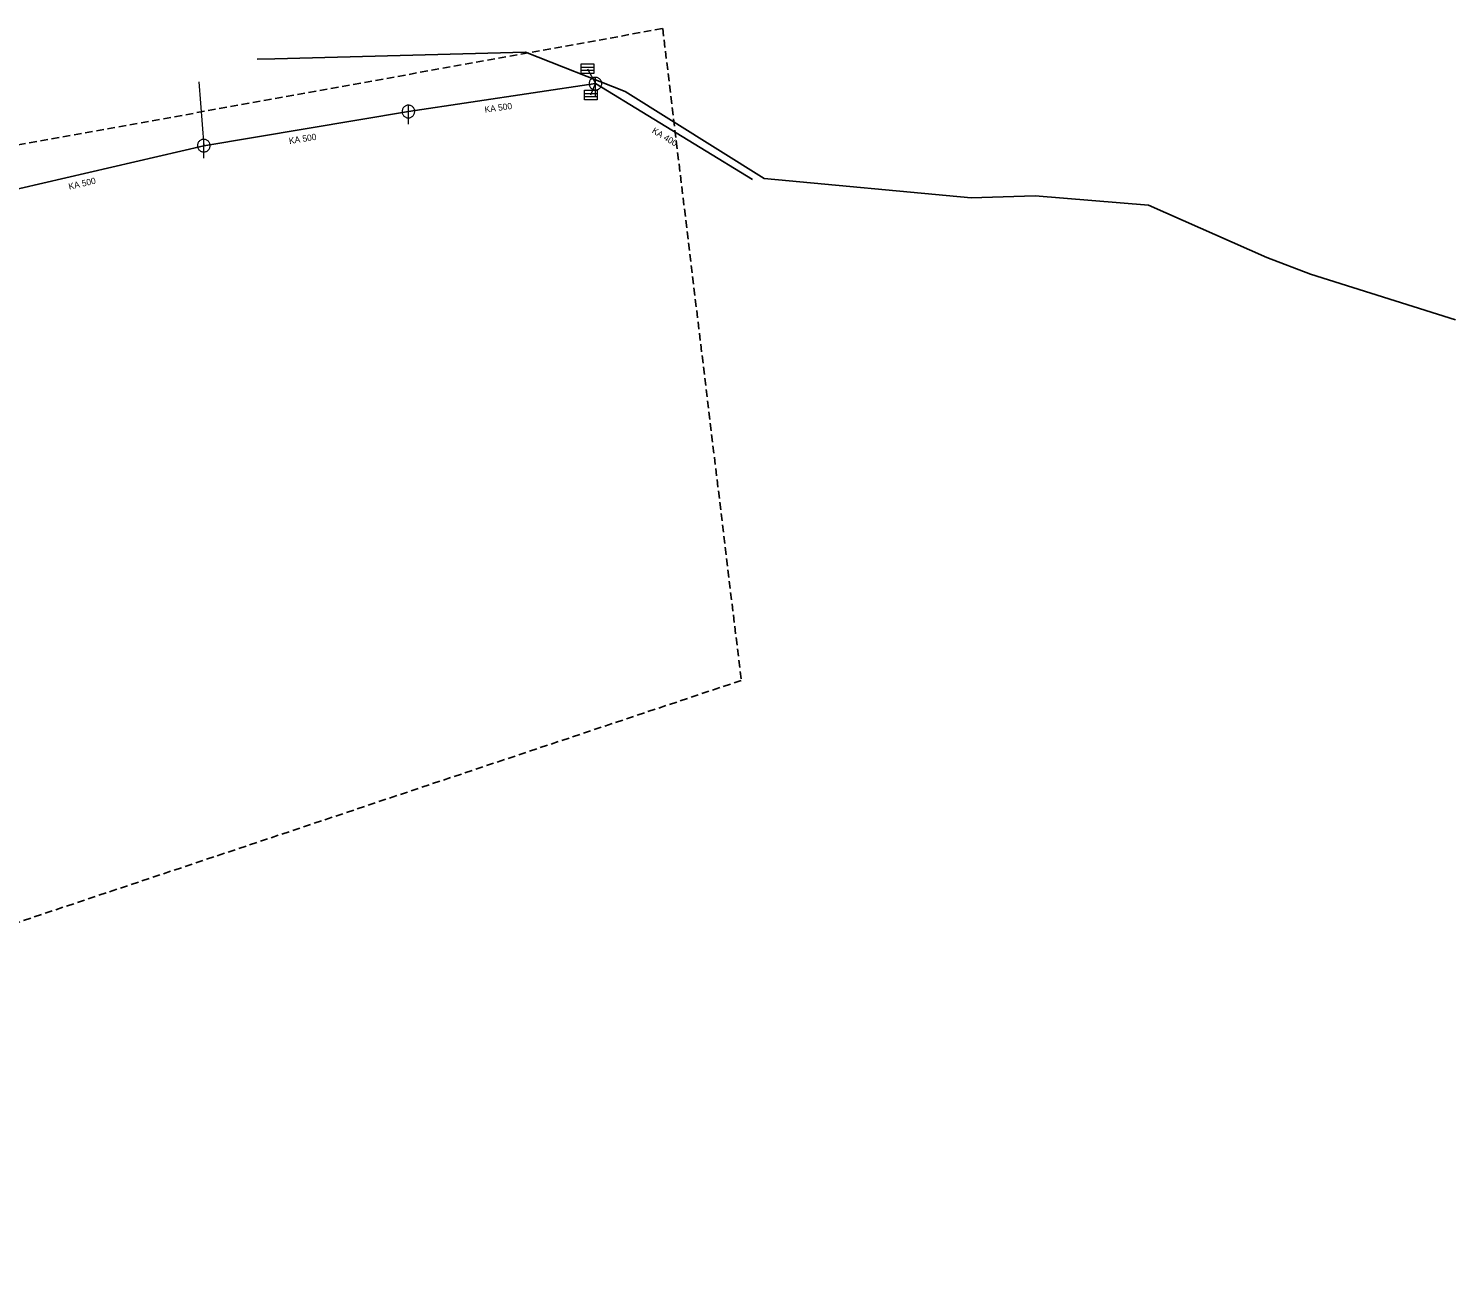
# Model space of a CAD drawing. Extents: x -687013 to -686506, y -973869 to -973672.
# Drawn here: x -686732.6 to -686506.3, y -973869.4 to -973671.6 of the extents above; entities that cross this region are included whole.
import ezdxf

# ---------------------------------------------------------------- set-up
doc = ezdxf.new("R2010")
doc.units = 0
doc.header["$LTSCALE"] = 0.4
doc.linetypes.add('MEDIUM_DASHED', pattern=[4.5, 3, -1.5])
doc.layers.add('1', color=7, linetype='Continuous')
for name, color, linetype, lineweight in [('11', 7, 'Continuous', 13), ('14', 7, 'Continuous', 25), ('17', 7, 'Continuous', 25), ('22', 7, 'Continuous', 13), ('63', 7, 'MEDIUM_DASHED', 25)]:
    doc.layers.add(name, color=color, linetype=linetype, lineweight=lineweight)

msp = doc.modelspace()

# ---------------------------------------------------------------- linework, layer by layer
at = {"layer": '11'}
for p, q in [((-686643.98, -973677.98), (-686642.71, -973680.34)), ((-686705.62, -973680.08), (-686704.81, -973690.17)), ((-686643.45, -973682.14), (-686642.71, -973680.34))]:
    msp.add_line(p, q, dxfattribs=at)
at = {"layer": '14'}
for p, q in [((-686642.71, -973680.34), (-686672.372, -973684.756)), ((-686617.8, -973695.539), (-686642.71, -973680.34)), ((-686672.372, -973684.756), (-686704.809, -973690.17)), ((-686704.809, -973690.17), (-686742.511, -973698.919))]:
    msp.add_line(p, q, dxfattribs=at)
at = {"layer": '17'}
msp.add_lwpolyline([(-686506.346, -973717.746), (-686529.344, -973710.524), (-686536.247, -973707.872), (-686555.026, -973699.577), (-686572.978, -973698.129), (-686583.112, -973698.418), (-686615.962, -973695.359), (-686637.993, -973681.581), (-686653.818, -973675.34), (-686693.532, -973676.405), (-686696.345, -973676.48)], dxfattribs=at)
at = {"layer": '22'}
for p, q in [((-686644.991, -973677.723), (-686642.991, -973677.723)), ((-686644.991, -973678.223), (-686642.991, -973678.223)), ((-686642.71, -973682.34), (-686642.709, -973679.34)), ((-686644.461, -973681.883), (-686642.461, -973681.883)), ((-686644.461, -973682.383), (-686642.461, -973682.383)), ((-686672.372, -973686.757), (-686672.371, -973683.757)), ((-686704.81, -973692.17), (-686704.809, -973689.17))]:
    msp.add_line(p, q, dxfattribs=at)
for points in [[(-686644.991, -973677.223), (-686642.991, -973677.223), (-686642.991, -973678.723), (-686644.991, -973678.723)], [(-686641.71, -973680.34), (-686641.715, -973680.231), (-686641.733, -973680.123), (-686641.763, -973680.017), (-686641.803, -973679.916), (-686641.855, -973679.819), (-686641.917, -973679.729), (-686641.989, -973679.646), (-686642.069, -973679.572), (-686642.157, -973679.506), (-686642.251, -973679.451), (-686642.351, -973679.406), (-686642.456, -973679.373), (-686642.563, -973679.351), (-686642.672, -973679.341), (-686642.782, -973679.343), (-686642.89, -973679.357), (-686642.997, -973679.382), (-686643.1, -973679.419), (-686643.198, -973679.468), (-686643.29, -973679.526), (-686643.376, -973679.595), (-686643.453, -973679.672), (-686643.522, -973679.758), (-686643.581, -973679.85), (-686643.629, -973679.948), (-686643.666, -973680.051), (-686643.692, -973680.158), (-686643.706, -973680.266), (-686643.709, -973680.376), (-686643.699, -973680.485), (-686643.678, -973680.592), (-686643.644, -973680.696), (-686643.6, -973680.796), (-686643.545, -973680.891), (-686643.479, -973680.979), (-686643.405, -973681.059), (-686643.322, -973681.131), (-686643.232, -973681.193), (-686643.136, -973681.245), (-686643.034, -973681.286), (-686642.929, -973681.316), (-686642.821, -973681.334), (-686642.711, -973681.34), (-686642.602, -973681.334), (-686642.494, -973681.316), (-686642.389, -973681.287), (-686642.287, -973681.246), (-686642.19, -973681.194), (-686642.1, -973681.132), (-686642.017, -973681.061), (-686641.942, -973680.981), (-686641.877, -973680.893), (-686641.821, -973680.799), (-686641.777, -973680.699), (-686641.743, -973680.595), (-686641.721, -973680.487), (-686641.711, -973680.378)], [(-686644.461, -973681.383), (-686642.461, -973681.383), (-686642.461, -973682.883), (-686644.461, -973682.883)], [(-686671.372, -973684.757), (-686671.377, -973684.648), (-686671.395, -973684.54), (-686671.425, -973684.434), (-686671.465, -973684.333), (-686671.517, -973684.236), (-686671.579, -973684.146), (-686671.651, -973684.063), (-686671.731, -973683.989), (-686671.819, -973683.923), (-686671.913, -973683.868), (-686672.013, -973683.823), (-686672.118, -973683.79), (-686672.225, -973683.768), (-686672.334, -973683.758), (-686672.444, -973683.76), (-686672.552, -973683.774), (-686672.659, -973683.799), (-686672.762, -973683.836), (-686672.86, -973683.885), (-686672.952, -973683.943), (-686673.038, -973684.012), (-686673.115, -973684.089), (-686673.184, -973684.175), (-686673.243, -973684.267), (-686673.291, -973684.365), (-686673.328, -973684.468), (-686673.354, -973684.575), (-686673.368, -973684.683), (-686673.371, -973684.793), (-686673.361, -973684.902), (-686673.34, -973685.009), (-686673.306, -973685.113), (-686673.262, -973685.213), (-686673.207, -973685.308), (-686673.141, -973685.396), (-686673.067, -973685.476), (-686672.984, -973685.548), (-686672.894, -973685.61), (-686672.798, -973685.662), (-686672.696, -973685.703), (-686672.591, -973685.733), (-686672.483, -973685.751), (-686672.373, -973685.757), (-686672.264, -973685.751), (-686672.156, -973685.733), (-686672.051, -973685.704), (-686671.949, -973685.663), (-686671.852, -973685.611), (-686671.762, -973685.549), (-686671.679, -973685.478), (-686671.604, -973685.398), (-686671.539, -973685.31), (-686671.483, -973685.216), (-686671.439, -973685.116), (-686671.405, -973685.012), (-686671.383, -973684.904), (-686671.373, -973684.795)], [(-686703.81, -973690.17), (-686703.815, -973690.061), (-686703.833, -973689.953), (-686703.863, -973689.847), (-686703.903, -973689.746), (-686703.955, -973689.649), (-686704.017, -973689.559), (-686704.089, -973689.476), (-686704.169, -973689.402), (-686704.257, -973689.336), (-686704.351, -973689.281), (-686704.451, -973689.236), (-686704.556, -973689.203), (-686704.663, -973689.181), (-686704.772, -973689.171), (-686704.882, -973689.173), (-686704.99, -973689.187), (-686705.097, -973689.212), (-686705.2, -973689.249), (-686705.298, -973689.298), (-686705.39, -973689.356), (-686705.476, -973689.425), (-686705.553, -973689.502), (-686705.622, -973689.588), (-686705.681, -973689.68), (-686705.729, -973689.778), (-686705.766, -973689.881), (-686705.792, -973689.988), (-686705.806, -973690.096), (-686705.809, -973690.206), (-686705.799, -973690.315), (-686705.778, -973690.422), (-686705.744, -973690.526), (-686705.7, -973690.626), (-686705.645, -973690.721), (-686705.579, -973690.809), (-686705.505, -973690.889), (-686705.422, -973690.961), (-686705.332, -973691.023), (-686705.236, -973691.075), (-686705.134, -973691.116), (-686705.029, -973691.146), (-686704.921, -973691.164), (-686704.811, -973691.17), (-686704.702, -973691.164), (-686704.594, -973691.146), (-686704.489, -973691.117), (-686704.387, -973691.076), (-686704.29, -973691.024), (-686704.2, -973690.962), (-686704.117, -973690.891), (-686704.042, -973690.811), (-686703.977, -973690.723), (-686703.921, -973690.629), (-686703.877, -973690.529), (-686703.843, -973690.425), (-686703.821, -973690.317), (-686703.811, -973690.208)]]:
    msp.add_lwpolyline(points, close=True, dxfattribs=at)
at = {"layer": '63'}
msp.add_lwpolyline([(-686909.784, -973869.363), (-686968.065, -973779.329), (-686968.065, -973779.329), (-686933.901, -973735.117), (-686933.901, -973735.117), (-686846.279, -973716.226), (-686846.279, -973716.226), (-686793.223, -973715.824), (-686793.223, -973715.824), (-686767.901, -973696.129), (-686767.901, -973696.129), (-686632.047, -973671.611), (-686632.047, -973671.611), (-686619.587, -973774.908), (-686619.587, -973774.908), (-686749.412, -973818.317), (-686749.412, -973818.317)], close=True, dxfattribs=at)

# ---------------------------------------------------------------- texts
at = {"layer": '1'}
for s, rotation, p in [('KA 500', 8, (-686660.215, -973684.953)), ('KA 400', 329, (-686633.849, -973688.071)), ('KA 500', 9, (-686691.222, -973689.914)), ('KA 500', 13, (-686726.133, -973697.156))]:
    msp.add_text(s, height=1, rotation=rotation, dxfattribs=at).set_placement(p)

doc.saveas('drawing.dxf')
